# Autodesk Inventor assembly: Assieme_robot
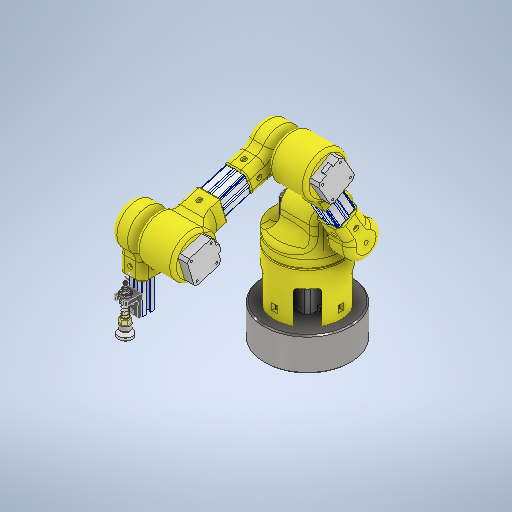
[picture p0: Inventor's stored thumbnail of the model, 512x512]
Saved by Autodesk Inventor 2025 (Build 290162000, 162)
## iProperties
Created: 2026-03
Part Number: Assieme_robot
Document SubType Name: Assembly
Designer: R5800u
Author: R5800u
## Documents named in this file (17)
- C:\Users\Ryzen5700u\Desktop\robot_cicloidale_singolo\Workgroups\NotInProject\Assieme_robot.iam
- C:\Users\Ryzen5700u\Desktop\robot_cicloidale_singolo\Workgroups\NotInProject\riduttore_cicloidale_nema17-47mm.iam
- C:\Users\Ryzen5700u\Desktop\robot_cicloidale_singolo\Workgroups\NotInProject\braccio1.ipt
- C:\Users\Ryzen5700u\Desktop\robot_cicloidale_singolo\Workgroups\NotInProject\tslot-20x20-100mm.ipt
- C:\Users\Ryzen5700u\Desktop\robot_cicloidale_singolo\Workgroups\NotInProject\riduttore_cicloidale_nema17-40mm.iam
- C:\Users\Ryzen5700u\Desktop\robot_cicloidale_singolo\Workgroups\NotInProject\base_ferro.ipt
- C:\Users\Ryzen5700u\Desktop\robot_cicloidale_singolo\Workgroups\NotInProject\ISO 104 - 1 11 50 x 70 x 14.ipt
- C:\Users\Ryzen5700u\Desktop\robot_cicloidale_singolo\Workgroups\NotInProject\blocco_base.ipt
- C:\Users\Ryzen5700u\Desktop\robot_cicloidale_singolo\Workgroups\NotInProject\disco_base1.ipt
- C:\Users\Ryzen5700u\Desktop\robot_cicloidale_singolo\Workgroups\NotInProject\disco_base2.ipt
- C:\Users\Ryzen5700u\Documents\Inventor\Content Center Files\R2025\it-IT\AS 1112 (2)\AS 1112 - M5  Tipo 5.ipt
- C:\Users\R5800u\Documents\Inventor\Content Center Files\R2025\it-IT\ANSI B18.3.1M(6)\ANSI B18.3.1M - M5x0,8 x 50(1).ipt
- C:\Users\Ryzen5700u\Desktop\robot_cicloidale_singolo\Workgroups\NotInProject\blocco_nema.ipt
- C:\Users\Ryzen5700u\Desktop\robot_cicloidale_singolo\Workgroups\NotInProject\blocco_albero_nema.ipt
- C:\Users\Ryzen5700u\Desktop\robot_cicloidale_singolo\Workgroups\NotInProject\ventosa_20mm.iam
- C:\Users\Ryzen5700u\Documents\Inventor\Content Center Files\R2025\it-IT\AS 1420\AS 1420 - 1973 - M3 x 16.ipt
- C:\Users\Ryzen5700u\Desktop\robot_cicloidale_singolo\Workgroups\NotInProject\Assieme_frame_tslot.iam
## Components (32 placed, 16 different names)
1. riduttore_cicloidale_nema17-47mm:1 [sub-assembly] — Allineato:1, Coincidente:7, Angolo:1, Coincidente:20, Rotazionale:2, Allineato:13, Coincidente:66
2. braccio1:1 — Coincidente:7, Angolo:1, Coincidente:10, Coincidente:11, Coincidente:56, Coincidente:59, Rotazionale:2
3. tslot-20x20-100mm:1
4. riduttore_cicloidale_nema17-40mm:1 [sub-assembly] — Coincidente:13, Allineato:3, Angolo:2, Coincidente:16, Coincidente:18
5. base_ferro:1
6. UNI ISO 104 1 11 50 x 70 x 14:1 — Coincidente:14, Coincidente:15
7. blocco_base:1
8. disco_base1:1 — Coincidente:16, Coincidente:17, Coincidente:19, Angolo:6
9. disco_base2:1 — Coincidente:18, Coincidente:19, Angolo:3, Coincidente:20
10. Vite forgiata a testa incassata - Metrico M5x0,8 x 50:1 — Coincidente:30
11. Vite forgiata a testa incassata - Metrico M5x0,8 x 50:2 — Coincidente:32
12. Vite forgiata a testa incassata - Metrico M5x0,8 x 50:3 — Coincidente:34
13. Vite forgiata a testa incassata - Metrico M5x0,8 x 50:4 — Coincidente:36
14. blocco_nema:1
15. riduttore_cicloidale_nema17-40mm:2 [sub-assembly] — Coincidente:39, Angolo:4, Allineato:10, Coincidente:40
16. blocco_albero_nema:1 — Coincidente:40, Coincidente:41, Coincidente:42, Coincidente:43, Coincidente:44
17. tslot-20x20-100mm:2
18. blocco_nema:2
19. riduttore_cicloidale_nema17-40mm:3 [sub-assembly] — Coincidente:47, Angolo:5, Coincidente:48, Coincidente:49
20. blocco_albero_nema:2 — Coincidente:49, Coincidente:50, Coincidente:51, Coincidente:52, Coincidente:53, Coincidente:55
21. ventosa_20mm:1 [sub-assembly] — Coincidente:51, Coincidente:52, Coincidente:53
22. AS 1420 - Metrico M3 x 16:1 — Coincidente:55
23. Assieme_frame_tslot:1 [sub-assembly] — Coincidente:57, Coincidente:58, Coincidente:59, Coincidente:63
24. Assieme_frame_tslot:2 [sub-assembly] — Coincidente:60, Coincidente:61, Coincidente:62
25. AS 1112 (2) - Metrico M5  Tipo 5:5
26. AS 1112 (2) - Metrico M5  Tipo 5:6
27. AS 1112 (2) - Metrico M5  Tipo 5:7
28. AS 1112 (2) - Metrico M5  Tipo 5:8
29. AS 1112 (2) - Metrico M5  Tipo 5:1
30. AS 1112 (2) - Metrico M5  Tipo 5:2
31. AS 1112 (2) - Metrico M5  Tipo 5:3
32. AS 1112 (2) - Metrico M5  Tipo 5:4
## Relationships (49: Mate 38, Angle 6, Flush 4, RevoluteJoint 1)
- Allineato:1 [Flush]: riduttore_cicloidale_nema17-47mm:1
- Coincidente:7 [Mate]: riduttore_cicloidale_nema17-47mm:1 ↔ braccio1:1
- Angolo:1 [Angle]: riduttore_cicloidale_nema17-47mm:1 ↔ braccio1:1
- Coincidente:10 [Mate]: braccio1:1
- Coincidente:11 [Mate]: braccio1:1
- Coincidente:13 [Mate]: riduttore_cicloidale_nema17-40mm:1
- Allineato:3 [Flush]: riduttore_cicloidale_nema17-40mm:1
- Coincidente:14 [Mate]: UNI ISO 104 1 11 50 x 70 x 14:1
- Coincidente:15 [Mate]: UNI ISO 104 1 11 50 x 70 x 14:1
- Angolo:2 [Angle]: riduttore_cicloidale_nema17-40mm:1
- Coincidente:16 [Mate]: riduttore_cicloidale_nema17-40mm:1 ↔ disco_base1:1
- Coincidente:17 [Mate]: disco_base1:1
- Coincidente:18 [Mate]: riduttore_cicloidale_nema17-40mm:1 ↔ disco_base2:1
- Coincidente:19 [Mate]: disco_base1:1 ↔ disco_base2:1
- Angolo:3 [Angle]: disco_base2:1
- Coincidente:20 [Mate]: riduttore_cicloidale_nema17-47mm:1 ↔ disco_base2:1
- Coincidente:30 [Mate]: Vite forgiata a testa incassata - Metrico M5x0,8 x 50:1
- Coincidente:32 [Mate]: Vite forgiata a testa incassata - Metrico M5x0,8 x 50:2
- Coincidente:34 [Mate]: Vite forgiata a testa incassata - Metrico M5x0,8 x 50:3
- Coincidente:36 [Mate]: Vite forgiata a testa incassata - Metrico M5x0,8 x 50:4
- Coincidente:39 [Mate]: riduttore_cicloidale_nema17-40mm:2
- Angolo:4 [Angle]: riduttore_cicloidale_nema17-40mm:2
- Allineato:10 [Flush]: riduttore_cicloidale_nema17-40mm:2
- Coincidente:40 [Mate]: riduttore_cicloidale_nema17-40mm:2 ↔ blocco_albero_nema:1
- Coincidente:41 [Mate]: blocco_albero_nema:1
- Coincidente:42 [Mate]: blocco_albero_nema:1
- Coincidente:43 [Mate]: blocco_albero_nema:1
- Coincidente:44 [Mate]: blocco_albero_nema:1
- Coincidente:47 [Mate]: riduttore_cicloidale_nema17-40mm:3
- Angolo:5 [Angle]: riduttore_cicloidale_nema17-40mm:3
- Coincidente:48 [Mate]: riduttore_cicloidale_nema17-40mm:3
- Coincidente:49 [Mate]: riduttore_cicloidale_nema17-40mm:3 ↔ blocco_albero_nema:2
- Coincidente:50 [Mate]: blocco_albero_nema:2
- Coincidente:51 [Mate]: blocco_albero_nema:2 ↔ ventosa_20mm:1
- Coincidente:52 [Mate]: blocco_albero_nema:2 ↔ ventosa_20mm:1
- Coincidente:53 [Mate]: blocco_albero_nema:2 ↔ ventosa_20mm:1
- Coincidente:55 [Mate]: blocco_albero_nema:2 ↔ AS 1420 - Metrico M3 x 16:1
- Angolo:6 [Angle]: disco_base1:1
- Coincidente:56 [Mate]: braccio1:1
- Coincidente:57 [Mate]: Assieme_frame_tslot:1
- Coincidente:58 [Mate]: Assieme_frame_tslot:1
- Coincidente:59 [Mate]: braccio1:1 ↔ Assieme_frame_tslot:1
- Coincidente:60 [Mate]: Assieme_frame_tslot:2
- Coincidente:61 [Mate]: Assieme_frame_tslot:2
- Coincidente:62 [Mate]: Assieme_frame_tslot:2
- Rotazionale:2 [RevoluteJoint]: riduttore_cicloidale_nema17-47mm:1 ↔ braccio1:1
- Coincidente:63 [Mate]: Assieme_frame_tslot:1
- Allineato:13 [Flush]: riduttore_cicloidale_nema17-47mm:1
- Coincidente:66 [Mate]: riduttore_cicloidale_nema17-47mm:1
